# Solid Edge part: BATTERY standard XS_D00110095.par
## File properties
Author: angelika.perkovic
Template: din part.par
Last saved by: Angelika.Perkovic
Revision: 81
Application: Solid Edge
Document Number: D00110095
Username: Angelika.Perkovic
Genauigkeit: 0,990
Dichte: 0,00786 kg/dm^3
CompactCalculationInitialized: 1
Title: BATTERY standard XS
Teileart: Eigenfertigung
Entstanden aus: D00108826
Version: 00.00
Bezeichnung1: BATTERY standard XS
Bezeichnung2: Typ 90, Sicherheitsschrank mit Flügeltüren
Dokumentnummer: D00110095
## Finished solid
Body 1: solid body, 96 faces, 189 edges, 98 vertices.
  Faces by surface: plane 68, cylinder 21, torus 5, cone 2
  Edges by curve: line 144, circle 43, ellipse 2
Bounding box of the edges (mm; curved faces can reach further): 1194.000 x 647.000 x 1691.000, from (0, -35, 0) to (1194, 612, 1691).
Cylindrical faces by radius (mm): R3.1 x2, R3.75 x2, R6 x6, R15 x4, R16 x2, R37.5 x3, R54.75 x2
Conical faces (half-angle, radius in mm at the cone's reference point): 20 deg R37.5 x1, 20.9929 deg R37.5 x1
Toroidal faces (ring radius, tube radius in mm): R9 r6 x4, R80.4965 r37.5 x1
Planar faces by outward normal: +x 11, +y 11, +z 14, -x 11, -y 12, -z 9
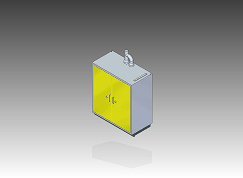
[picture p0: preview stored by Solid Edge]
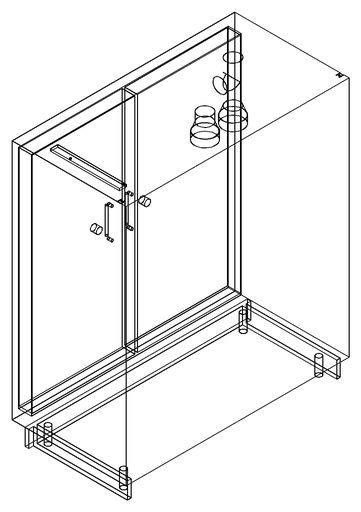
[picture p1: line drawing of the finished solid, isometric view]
